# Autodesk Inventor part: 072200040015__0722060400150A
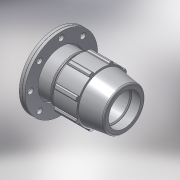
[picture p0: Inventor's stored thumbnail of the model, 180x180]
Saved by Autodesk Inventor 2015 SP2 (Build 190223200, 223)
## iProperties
Created: 2017-02
Part Number: 072200040015__0722060400150A
Material: PVC-Piping
Description: PLASSON COMPRESSION FLANGE ADAPTOR 40-1.1/2"
Document SubType Name: Modeling
Designer: KIM
Mass: 92.6774 g
Surface Area: 199.44 cm^2
Volume: 66.1981 cm^3
Density: 1.4 g/cm^3
Appearance: Smooth - White
Author: KIM
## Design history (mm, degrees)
derived "07220.ipt"
feature "Solid1::07220.ipt"
tag "TaggingFeature1"
body "Solid1"
other parameters: "d4" = 17, "d5" = 38.08, "d7" = 82, "d9" = 17, "d11" = 3.4, "d12" = 65.6, "d13" = 120 deg, "d14" = 52, "d15" = 12 deg, "d18" = 2, "d19" = 35 deg, "d20" = 17.5 deg, "d21" = 76.26, "d23" = 0, "d25" = 360 deg, "d27" = 1.64, "d42" = 41.65, "d43" = 2.46, "d46" = 1.2, "d53" = 0.8, "d67" = 4.1, "d68" = 93, "d70" = 119, "d73" = 9.91667, "d74" = 90 deg, "d75" = 0.3, "d77" = 18, "d78" = 55, "d80" = 0, "d82" = 360 deg, "d85" = 69.7, "d86" = 65.6, "d87" = 0.75, "d93" = 5.95, "d95" = 36, "d96" = 0.3, "d99" = 360 deg, "E_" = 82, "H_" = 119, "l_" = 93, "S_" = 18
